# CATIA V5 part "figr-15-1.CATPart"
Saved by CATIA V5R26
Part number: Part1
Bounding box of the stored display mesh (mm): x -92.657 to 112.488, y -68.408 to 38.341, z -24 to 61.972
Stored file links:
  D:\_Deepak\CATIA\CATIA V5-6R2016_Deepak\Resources\Part files\Partfiles\c15_catia_v5_6r2016_prt\figr-15-1.CATPart
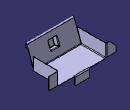
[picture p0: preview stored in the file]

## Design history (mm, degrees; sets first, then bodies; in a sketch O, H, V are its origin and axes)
SheetMetalParameters1: Thickness 1, BendRadius 2, KFactor 0.400515 {= log(min(100,max(20*SheetMetalParameters1.BendRadius,SheetMetalParameters1.Thickness)/SheetMetalParameters1.Thickness))/log(100)/2}, ReliefRadialLength 1, ReliefAxialLength 2, WallPerLength 50, MinimumBendRadius 0
Body1 (main body)
  Sketch1 on xy-plane, origin (0, 0, 0), H (1, 0, 0), V (0, 1, 0)
    line L1 (-62.6567, 37.3409) -> (82.4875, 37.3409)
    line L2 (82.4875, 37.3409) -> (82.4875, -38.1848)
    line L3 (82.4875, -38.1848) -> (-62.6567, -38.1848)
    line L4 (-62.6567, -38.1848) -> (-62.6567, 37.3409)
    horizontal: L1 H, L3 H
    vertical: L2 V, L4 V
  Wall1: Thickness 1, Profile Sketch1, OffsetValue 0
  d_NewWallOnEdge1: NewWallOnEdge_Length 25, NewWallOnEdge_HeightLimitOffset 0, NewWallOnEdge_WidthOffset1 -50, NewWallOnEdge_WidthOffset2 -50, NewWallOnEdge_Angle 90, NewWallOnEdge_BendRadiusValue 2 {= SheetMetalParameters1.BendRadius}, NewWallOnEdge_BendTable SheetMetalParameters1, NewWallOnEdge_Edge edge [face of Wall1 | face of Wall1], NewWallOnEdge_GapValue 0, KFacteur 0.400515 {= log(min(100,max(20*d_NewWallOnEdge1.Radius,SheetMetalParameters1.Thickness)/SheetMetalParameters1.Thickness))/log(100)/2}
  d_NewWallOnEdge2: NewWallOnEdge_Length 40, NewWallOnEdge_HeightLimitOffset 0, NewWallOnEdge_WidthOffset1 0, NewWallOnEdge_WidthOffset2 0, NewWallOnEdge_Angle 90, NewWallOnEdge_BendRadiusValue 2 {= SheetMetalParameters1.BendRadius}, NewWallOnEdge_BendTable SheetMetalParameters1, NewWallOnEdge_Edge edge [face of Wall1 | face of Wall1], NewWallOnEdge_GapValue 0, KFacteur 0.400515 {= log(min(100,max(20*d_NewWallOnEdge2.Radius,SheetMetalParameters1.Thickness)/SheetMetalParameters1.Thickness))/log(100)/2}
  d_NewWallOnEdge3: NewWallOnEdge_Length 30, NewWallOnEdge_HeightLimitOffset 0, NewWallOnEdge_WidthOffset1 0, NewWallOnEdge_WidthOffset2 0, NewWallOnEdge_Angle 90, NewWallOnEdge_BendRadiusValue 2 {= SheetMetalParameters1.BendRadius}, NewWallOnEdge_BendTable SheetMetalParameters1, NewWallOnEdge_Edge edge [face of d_NewWallOnEdge2 | face of d_NewWallOnEdge2], NewWallOnEdge_GapValue 0, KFacteur 0.400515 {= log(min(100,max(20*d_NewWallOnEdge3.Radius,SheetMetalParameters1.Thickness)/SheetMetalParameters1.Thickness))/log(100)/2}
  d_NewWallOnEdge4: NewWallOnEdge_Length 60, NewWallOnEdge_HeightLimitOffset 0, NewWallOnEdge_WidthOffset1 0, NewWallOnEdge_WidthOffset2 0, NewWallOnEdge_Angle 110, NewWallOnEdge_BendRadiusValue 2 {= SheetMetalParameters1.BendRadius}, NewWallOnEdge_BendTable SheetMetalParameters1, NewWallOnEdge_Edge edge [face of Wall1 | face of Wall1], NewWallOnEdge_GapValue 0, KFacteur 0.400515 {= log(min(100,max(20*d_NewWallOnEdge4.Radius,SheetMetalParameters1.Thickness)/SheetMetalParameters1.Thickness))/log(100)/2}
  Flange1: Angle 90, Length 10, Radius 2 {= SheetMetalParameters1.BendRadius}, KFacteur 0.400515 {= log(min(100,max(20*Flange1.Radius,SheetMetalParameters1.Thickness)/SheetMetalParameters1.Thickness))/log(100)/2}, Guide edge [face of d_NewWallOnEdge4 | face of d_NewWallOnEdge4]
  d_NewWallOnEdge5: NewWallOnEdge_Length 40, NewWallOnEdge_HeightLimitOffset 0, NewWallOnEdge_WidthLimit2 face of d_NewWallOnEdge4, NewWallOnEdge_WidthOffset1 0, NewWallOnEdge_WidthOffset2 -2, NewWallOnEdge_Angle 90, NewWallOnEdge_WithBend true, NewWallOnEdge_BendRadiusValue 2 {= SheetMetalParameters1.BendRadius}, NewWallOnEdge_BendTable SheetMetalParameters1, NewWallOnEdge_Edge edge [face of Wall1 | face of Wall1], NewWallOnEdge_GapValue 0, KFacteur 0.400515 {= log(min(100,max(20*d_NewWallOnEdge5.Radius,SheetMetalParameters1.Thickness)/SheetMetalParameters1.Thickness))/log(100)/2}
  d_NewWallOnEdge6: NewWallOnEdge_Length 30, NewWallOnEdge_HeightLimitOffset 0, NewWallOnEdge_WidthOffset1 0, NewWallOnEdge_WidthOffset2 0, NewWallOnEdge_Angle 90, NewWallOnEdge_BendRadiusValue 2 {= SheetMetalParameters1.BendRadius}, NewWallOnEdge_BendTable SheetMetalParameters1, NewWallOnEdge_Edge edge [face of d_NewWallOnEdge5 | face of d_NewWallOnEdge5], NewWallOnEdge_GapValue 0, KFacteur 0.400515 {= log(min(100,max(20*d_NewWallOnEdge6.Radius,SheetMetalParameters1.Thickness)/SheetMetalParameters1.Thickness))/log(100)/2}
  Chamfer1: ChamferAngle 45, ChamferLength1 20, ChamferLength2 0.5, ChamferPropagation 1, ChamferReverse false, ChamferType 1, CornerChamferEdges edge [face of d_NewWallOnEdge6 | face of d_NewWallOnEdge6]
  Corner1: CornerRadius 3, CornerChamferEdges (edge [face of d_NewWallOnEdge1 | face of d_NewWallOnEdge1]; edge [face of d_NewWallOnEdge1 | face of d_NewWallOnEdge1])
  Sketch2 on face of d_NewWallOnEdge4, origin (8.9154, -38.1848, 1), H (1, 0, 0), V (0, -0.342, 0.9397)
    line L1 (-12.2908, 45.4061) -> (12.3784, 45.4061)
    line L2 (12.3784, 45.4061) -> (12.3784, 21.719)
    line L3 (12.3784, 21.719) -> (-12.2908, 21.719)
    line L4 (-12.2908, 21.719) -> (-12.2908, 45.4061)
    horizontal: L1 H, L3 H
    vertical: L2 V, L4 V
  d_Stamp1: NewRoot_AttribNormalisation "No Standard", Stamp_FilletRadius 1, Stamp_IntersectFilletRadius 2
